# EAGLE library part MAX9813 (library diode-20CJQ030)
Maxim's MAX9813 Tiny, Low-Cost, Single/Dual-Input, Fixed-Gain Microphone Amplifiers with Integrated Bias Description: The MAX9812/MAX9813 are single/dual-input, 20dB fixed-gain microphone amplifiers. They offer tiny packaging and a low-noise, integrated microphone bias, making them ideal for portable audio applications such as notebook computers, cell phones, and PDAs. These amplifiers feature a 500kHz bandwidth, Rail-to-Rail® outputs, an industry-leading 100dB power-supply rejection ratio, and a very low 0.015% THD+N. Power-saving features include very low 230uA supply current and a total shutdown mode that cuts the combined supply and BIAS currents to only 100nA. The MAX9812 is a single amplifier in a 6-pin SC70 package (2mm x 2.1mm) and the MAX9813 is a dualinput amplifier available in an 8-pin SOT23 (3mm x 3mm) package. The MAX9813 has two inputs allowing two microphones to be multiplexed to a single output. The MAX9812/MAX9813 are offered in two grades. The MAX9812L/MAX9813L are optimized for 3.3V supply operation (2.7V to 3.6V). The MAX9812H/MAX9813H are PC2001 compliant and are optimized for 5V operation (4.5V to 5.5V). Both devices are specified over the -40°C to +85°C extended operating temperature range. Features: PC2001 Compliant 100dB at 217Hz Power-Supply Rejection Ratio Very Low 230?A Quiescent Current Low 0.015% THD+N Available in Two Versions: - MAX9812L/MAX9813L 2.7V to 3.6V - MAX9812H/MAX9813H 4.5V to 5.5V Internal Low-Noise Microphone Bias Supply - 2.3V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
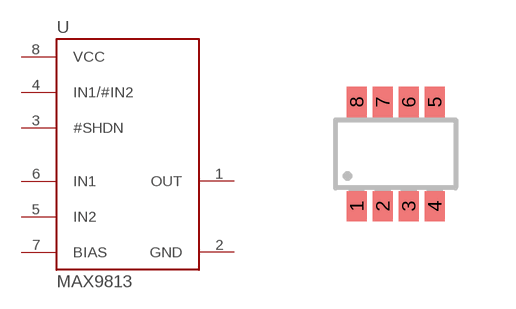
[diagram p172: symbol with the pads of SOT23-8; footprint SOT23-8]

Designator prefix U

## MAX9813  [SOT23-8]
1  OUT  out
2  GND  pwr
3  #SHDN  in
4  IN1/#IN2  in
5  IN2  in
6  IN1  in
7  BIAS  in
8  VCC  pwr

## Footprint SOT23-8 (pad centres in mm)
SOT23-8 package for Maxim's MAX9813
smd 0.5 x 0.75: 1 -0.975,-1.3; 2 -0.325,-1.3; 3 0.325,-1.3; 4 0.975,-1.3; 5 0.975,1.3; 6 0.325,1.3; 7 -0.325,1.3; 8 -0.975,1.3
